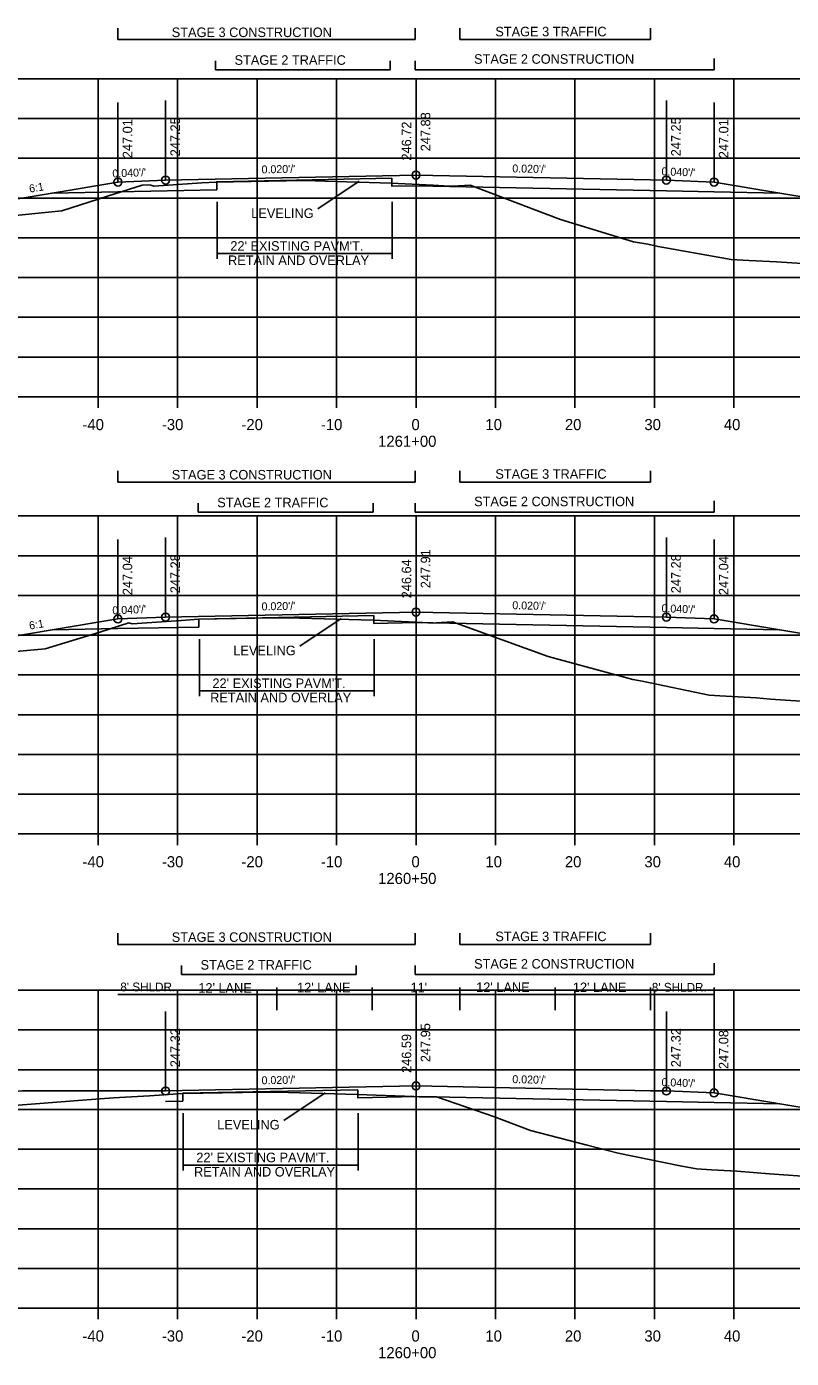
# Model space of a CAD drawing. Extents: x 1342547 to 1344156, y -1532351 to -1517216.
# Drawn here: x 1342653.9 to 1342750.1, y -1525728.6 to -1525561.1 of the extents above; entities that cross this region are included whole.
import ezdxf

# ---------------------------------------------------------------- set-up
doc = ezdxf.new("R2010")
doc.units = 0
for name, color, linetype in [('R_Alt Surface', 7, 'Continuous'), ('R_Axis', 7, 'Continuous'), ('R_Axis Annot', 7, 'Continuous'), ('R_Draft', 7, 'Continuous'), ('R_Drive', 7, 'Continuous'), ('R_Exist Surface', 7, 'Continuous'), ('R_Fin Surface', 7, 'Continuous'), ('R_Grid', 7, 'Continuous'), ('R_No Plot', 7, 'Continuous'), ('R_Xsect Elev', 7, 'Continuous'), ('R_Xsect Slope', 7, 'Continuous')]:
    doc.layers.add(name, color=color, linetype=linetype)

msp = doc.modelspace()

# ---------------------------------------------------------------- linework, layer by layer
at = {"layer": 'R_Alt Surface'}
for points in [[(1342677.81, -1525581.63), (1342677.81, -1525580.63), (1342699.84, -1525580.19)], [(1342699.84, -1525580.19), (1342699.84, -1525581.19), (1342702.87, -1525581.13)], [(1342740.37, -1525581.88), (1342734.37, -1525581.76), (1342702.87, -1525581.13)], [(1342657.09, -1525582.04), (1342665.37, -1525581.88)], [(1342665.37, -1525581.88), (1342677.81, -1525581.63)], [(1342740.37, -1525581.88), (1342748.64, -1525582.04)], [(1342675.56, -1525636.64), (1342675.56, -1525635.64), (1342697.58, -1525635.2)], [(1342697.58, -1525635.2), (1342697.58, -1525636.2), (1342702.87, -1525636.09)], [(1342740.37, -1525636.84), (1342734.37, -1525636.72), (1342702.87, -1525636.09)], [(1342657.09, -1525637.01), (1342665.37, -1525636.84)], [(1342665.37, -1525636.84), (1342675.56, -1525636.64)], [(1342740.37, -1525636.84), (1342748.64, -1525637.01)], [(1342673.53, -1525696.3), (1342673.53, -1525695.3), (1342695.55, -1525694.86)], [(1342695.55, -1525694.86), (1342695.55, -1525695.86), (1342702.87, -1525695.71)], [(1342671.37, -1525696.34), (1342673.53, -1525696.3)], [(1342740.37, -1525696.46), (1342734.37, -1525696.34), (1342702.87, -1525695.71)], [(1342740.37, -1525696.46), (1342748.64, -1525696.63)]]:
    msp.add_lwpolyline(points, dxfattribs=at)
at = {"layer": 'R_Axis'}
for p, q in [((1342562.87, -1525607.67), (1342842.87, -1525607.67)), ((1342662.87, -1525609.07), (1342662.87, -1525607.67)), ((1342672.87, -1525609.07), (1342672.87, -1525607.67)), ((1342682.87, -1525609.07), (1342682.87, -1525607.67)), ((1342692.87, -1525609.07), (1342692.87, -1525607.67)), ((1342702.87, -1525609.07), (1342702.87, -1525607.67)), ((1342712.87, -1525609.07), (1342712.87, -1525607.67)), ((1342722.87, -1525609.07), (1342722.87, -1525607.67)), ((1342732.87, -1525609.07), (1342732.87, -1525607.67)), ((1342742.87, -1525609.07), (1342742.87, -1525607.67)), ((1342562.87, -1525662.67), (1342842.87, -1525662.67)), ((1342662.87, -1525664.07), (1342662.87, -1525662.67)), ((1342672.87, -1525664.07), (1342672.87, -1525662.67)), ((1342682.87, -1525664.07), (1342682.87, -1525662.67)), ((1342692.87, -1525664.07), (1342692.87, -1525662.67)), ((1342702.87, -1525664.07), (1342702.87, -1525662.67)), ((1342712.87, -1525664.07), (1342712.87, -1525662.67)), ((1342722.87, -1525664.07), (1342722.87, -1525662.67)), ((1342732.87, -1525664.07), (1342732.87, -1525662.67)), ((1342742.87, -1525664.07), (1342742.87, -1525662.67)), ((1342562.87, -1525722.33), (1342842.87, -1525722.33)), ((1342662.87, -1525723.73), (1342662.87, -1525722.33)), ((1342672.87, -1525723.73), (1342672.87, -1525722.33)), ((1342682.87, -1525723.73), (1342682.87, -1525722.33)), ((1342692.87, -1525723.73), (1342692.87, -1525722.33)), ((1342702.87, -1525723.73), (1342702.87, -1525722.33)), ((1342712.87, -1525723.73), (1342712.87, -1525722.33)), ((1342722.87, -1525723.73), (1342722.87, -1525722.33)), ((1342732.87, -1525723.73), (1342732.87, -1525722.33)), ((1342742.87, -1525723.73), (1342742.87, -1525722.33))]:
    msp.add_line(p, q, dxfattribs=at)
at = {"layer": 'R_Draft'}
for p, q in [((1342665.37, -1525562.74), (1342665.37, -1525561.31)), ((1342702.78, -1525562.74), (1342702.78, -1525561.31)), ((1342708.37, -1525562.74), (1342708.37, -1525561.31)), ((1342732.37, -1525562.74), (1342732.37, -1525561.31)), ((1342665.37, -1525562.74), (1342702.78, -1525562.74)), ((1342708.37, -1525562.74), (1342732.37, -1525562.74)), ((1342677.64, -1525566.54), (1342677.64, -1525565.39)), ((1342699.64, -1525566.54), (1342699.64, -1525565.39)), ((1342702.78, -1525566.54), (1342702.78, -1525565.39)), ((1342740.38, -1525566.54), (1342740.38, -1525565.11)), ((1342677.64, -1525566.54), (1342699.64, -1525566.54)), ((1342702.78, -1525566.54), (1342740.38, -1525566.54)), ((1342677.87, -1525583.14), (1342677.87, -1525590.34)), ((1342699.87, -1525583.14), (1342699.87, -1525590.34)), ((1342677.87, -1525589.67), (1342699.87, -1525589.67)), ((1342665.37, -1525618.41), (1342665.37, -1525616.98)), ((1342702.78, -1525618.41), (1342702.78, -1525616.98)), ((1342708.37, -1525618.41), (1342708.37, -1525616.98)), ((1342732.37, -1525618.41), (1342732.37, -1525616.98)), ((1342665.37, -1525618.41), (1342702.78, -1525618.41)), ((1342708.37, -1525618.41), (1342732.37, -1525618.41)), ((1342675.45, -1525622.21), (1342675.45, -1525621.06)), ((1342697.46, -1525622.21), (1342697.46, -1525621.06)), ((1342702.78, -1525622.21), (1342702.78, -1525621.06)), ((1342740.38, -1525622.21), (1342740.38, -1525620.77)), ((1342675.45, -1525622.21), (1342697.46, -1525622.21)), ((1342702.78, -1525622.21), (1342740.38, -1525622.21)), ((1342675.62, -1525638.15), (1342675.62, -1525645.35)), ((1342697.62, -1525638.15), (1342697.62, -1525645.35)), ((1342675.62, -1525644.68), (1342697.62, -1525644.68)), ((1342665.37, -1525676.58), (1342665.37, -1525675.14)), ((1342665.37, -1525676.58), (1342702.78, -1525676.58)), ((1342702.78, -1525676.58), (1342702.78, -1525675.14)), ((1342708.37, -1525676.58), (1342708.37, -1525675.14)), ((1342708.37, -1525676.58), (1342732.37, -1525676.58)), ((1342732.37, -1525676.58), (1342732.37, -1525675.14)), ((1342673.36, -1525680.37), (1342673.36, -1525679.23)), ((1342695.36, -1525680.37), (1342695.36, -1525679.23)), ((1342702.78, -1525680.37), (1342702.78, -1525679.23)), ((1342740.38, -1525680.37), (1342740.38, -1525678.94)), ((1342673.36, -1525680.37), (1342695.36, -1525680.37)), ((1342702.78, -1525680.37), (1342740.38, -1525680.37)), ((1342673.59, -1525697.81), (1342673.59, -1525705.01)), ((1342695.59, -1525697.81), (1342695.59, -1525705.01)), ((1342673.59, -1525704.34), (1342695.59, -1525704.34))]:
    msp.add_line(p, q, dxfattribs=at)
at = {"layer": 'R_Drive'}
msp.add_lwpolyline([(1342581.05, -1525700.81), (1342653.37, -1525694.97), (1342671.37, -1525695.01)], dxfattribs=at)
at = {"layer": 'R_Exist Surface'}
for points in [[(1342650.35, -1525585.09), (1342658.31, -1525584.3), (1342664.04, -1525582.45), (1342668.42, -1525581.04), (1342669.2, -1525580.99), (1342669.52, -1525581.06), (1342669.88, -1525581.17), (1342675.94, -1525580.77), (1342677.73, -1525580.67), (1342686.55, -1525580.51), (1342688.92, -1525580.47), (1342691.4, -1525580.54), (1342699.76, -1525580.8), (1342705.01, -1525581.06), (1342707.03, -1525581.16), (1342707.5, -1525581.16), (1342709.7, -1525581.04), (1342717.6, -1525584.07), (1342721.06, -1525585.39), (1342729.29, -1525587.89), (1342730.22, -1525588.17), (1342732.05, -1525588.49), (1342733.33, -1525588.77), (1342742.53, -1525590.4), (1342744.75, -1525590.51), (1342748.24, -1525590.68), (1342753.37, -1525591.03)], [(1342647.41, -1525640.18), (1342656.21, -1525639.38), (1342663.1, -1525637.29), (1342666.75, -1525636.13), (1342666.88, -1525636.16), (1342667.18, -1525636.23), (1342673.33, -1525635.82), (1342675.52, -1525635.67), (1342684.99, -1525635.5), (1342686.59, -1525635.47), (1342688.22, -1525635.52), (1342697.52, -1525635.79), (1342703.69, -1525636.07), (1342705.02, -1525636.14), (1342705.39, -1525636.11), (1342707.46, -1525635.99), (1342719.5, -1525640.35), (1342730.15, -1525643.23), (1342731.33, -1525643.47), (1342739.75, -1525645.2), (1342741.08, -1525645.28), (1342745.7, -1525645.56), (1342747.49, -1525645.7), (1342752.56, -1525646.04)], [(1342651.77, -1525696.89), (1342660.92, -1525696.15), (1342664.82, -1525695.88), (1342669.33, -1525695.6), (1342673.53, -1525695.33), (1342683.56, -1525695.15), (1342684.48, -1525695.14), (1342685.37, -1525695.16), (1342695.5, -1525695.44), (1342702.58, -1525695.72), (1342703.28, -1525695.75), (1342703.45, -1525695.74), (1342705.44, -1525695.75), (1342712.74, -1525698.27), (1342717.29, -1525699.97), (1342724.39, -1525701.84), (1342728.29, -1525702.83), (1342736.12, -1525704.41), (1342738.17, -1525704.81), (1342740.04, -1525704.91), (1342743.23, -1525705.09), (1342747.35, -1525705.43), (1342751.51, -1525705.74)]]:
    msp.add_lwpolyline(points, dxfattribs=at)
at = {"layer": 'R_Fin Surface'}
for points in [[(1342612.36, -1525593.42), (1342614.23, -1525594.04), (1342643.37, -1525584.33), (1342657.09, -1525582.04), (1342665.37, -1525580.66), (1342671.37, -1525580.42), (1342673.37, -1525580.38), (1342702.87, -1525579.79), (1342732.37, -1525580.38), (1342734.37, -1525580.42), (1342740.37, -1525580.66), (1342748.64, -1525582.04), (1342762.37, -1525584.33), (1342783.17, -1525591.27)], [(1342608.75, -1525647.55), (1342613.68, -1525649.19), (1342643.37, -1525639.29), (1342657.09, -1525637.01), (1342665.37, -1525635.63), (1342671.37, -1525635.39), (1342673.37, -1525635.35), (1342702.87, -1525634.76), (1342732.37, -1525635.35), (1342734.37, -1525635.39), (1342740.37, -1525635.63), (1342748.64, -1525637.01), (1342762.37, -1525639.29), (1342783.37, -1525646.3)], [(1342671.37, -1525695.01), (1342702.87, -1525694.38), (1342732.37, -1525694.97), (1342734.37, -1525695.01), (1342740.37, -1525695.25), (1342748.64, -1525696.63), (1342762.37, -1525698.91), (1342783.8, -1525706.06)]]:
    msp.add_lwpolyline(points, dxfattribs=at)
at = {"layer": 'R_Grid'}
for p, q in [((1342562.87, -1525567.67), (1342842.87, -1525567.67)), ((1342662.87, -1525607.67), (1342662.87, -1525567.67)), ((1342672.87, -1525607.67), (1342672.87, -1525567.67)), ((1342682.87, -1525607.67), (1342682.87, -1525567.67)), ((1342692.87, -1525607.67), (1342692.87, -1525567.67)), ((1342702.87, -1525607.67), (1342702.87, -1525567.67)), ((1342712.87, -1525607.67), (1342712.87, -1525567.67)), ((1342722.87, -1525607.67), (1342722.87, -1525567.67)), ((1342732.87, -1525607.67), (1342732.87, -1525567.67)), ((1342742.87, -1525607.67), (1342742.87, -1525567.67)), ((1342562.87, -1525572.67), (1342842.87, -1525572.67)), ((1342562.87, -1525577.67), (1342842.87, -1525577.67)), ((1342562.87, -1525582.67), (1342842.87, -1525582.67)), ((1342562.87, -1525587.67), (1342842.87, -1525587.67)), ((1342562.87, -1525592.67), (1342842.87, -1525592.67)), ((1342562.87, -1525597.67), (1342842.87, -1525597.67)), ((1342562.87, -1525602.67), (1342842.87, -1525602.67)), ((1342562.87, -1525607.67), (1342842.87, -1525607.67)), ((1342562.87, -1525622.67), (1342842.87, -1525622.67)), ((1342662.87, -1525662.67), (1342662.87, -1525622.67)), ((1342672.87, -1525662.67), (1342672.87, -1525622.67)), ((1342682.87, -1525662.67), (1342682.87, -1525622.67)), ((1342692.87, -1525662.67), (1342692.87, -1525622.67)), ((1342702.87, -1525662.67), (1342702.87, -1525622.67)), ((1342712.87, -1525662.67), (1342712.87, -1525622.67)), ((1342722.87, -1525662.67), (1342722.87, -1525622.67)), ((1342732.87, -1525662.67), (1342732.87, -1525622.67)), ((1342742.87, -1525662.67), (1342742.87, -1525622.67)), ((1342562.87, -1525627.67), (1342842.87, -1525627.67)), ((1342562.87, -1525632.67), (1342842.87, -1525632.67)), ((1342562.87, -1525637.67), (1342842.87, -1525637.67)), ((1342562.87, -1525642.67), (1342842.87, -1525642.67)), ((1342562.87, -1525647.67), (1342842.87, -1525647.67)), ((1342562.87, -1525652.67), (1342842.87, -1525652.67)), ((1342562.87, -1525657.67), (1342842.87, -1525657.67)), ((1342562.87, -1525662.67), (1342842.87, -1525662.67)), ((1342562.87, -1525682.33), (1342842.87, -1525682.33)), ((1342662.87, -1525722.33), (1342662.87, -1525682.33)), ((1342672.87, -1525722.33), (1342672.87, -1525682.33)), ((1342682.87, -1525722.33), (1342682.87, -1525682.33)), ((1342692.87, -1525722.33), (1342692.87, -1525682.33)), ((1342702.87, -1525722.33), (1342702.87, -1525682.33)), ((1342712.87, -1525722.33), (1342712.87, -1525682.33)), ((1342722.87, -1525722.33), (1342722.87, -1525682.33)), ((1342732.87, -1525722.33), (1342732.87, -1525682.33)), ((1342742.87, -1525722.33), (1342742.87, -1525682.33)), ((1342562.87, -1525687.33), (1342842.87, -1525687.33)), ((1342562.87, -1525692.33), (1342842.87, -1525692.33)), ((1342562.87, -1525697.33), (1342842.87, -1525697.33)), ((1342562.87, -1525702.33), (1342842.87, -1525702.33)), ((1342562.87, -1525707.33), (1342842.87, -1525707.33)), ((1342562.87, -1525712.33), (1342842.87, -1525712.33)), ((1342562.87, -1525717.33), (1342842.87, -1525717.33)), ((1342562.87, -1525722.33), (1342842.87, -1525722.33))]:
    msp.add_line(p, q, dxfattribs=at)
at = {"layer": 'R_No Plot'}
for centre in [(1342702.87, -1525579.79), (1342665.37, -1525580.66), (1342671.37, -1525580.42), (1342734.37, -1525580.42), (1342740.37, -1525580.66), (1342702.87, -1525634.76), (1342665.37, -1525635.63), (1342671.37, -1525635.39), (1342734.37, -1525635.39), (1342740.37, -1525635.63), (1342671.37, -1525695.01), (1342702.87, -1525694.38), (1342734.37, -1525695.01), (1342740.37, -1525695.25)]:
    msp.add_circle(centre, 0.5, dxfattribs=at)
at = {"layer": 'R_Xsect Elev'}
for p, q in [((1342665.37, -1525580.66), (1342665.37, -1525570.66)), ((1342671.37, -1525580.42), (1342671.37, -1525570.42)), ((1342702.87, -1525579.79), (1342702.87, -1525569.79)), ((1342702.87, -1525580.96), (1342702.87, -1525570.96)), ((1342734.37, -1525580.42), (1342734.37, -1525570.42)), ((1342740.37, -1525580.66), (1342740.37, -1525570.66)), ((1342695.72, -1525580.56), (1342690.52, -1525584.05)), ((1342665.37, -1525635.63), (1342665.37, -1525625.63)), ((1342671.37, -1525635.39), (1342671.37, -1525625.39)), ((1342702.87, -1525634.76), (1342702.87, -1525624.76)), ((1342702.87, -1525636.03), (1342702.87, -1525626.03)), ((1342734.37, -1525635.39), (1342734.37, -1525625.39)), ((1342740.37, -1525635.63), (1342740.37, -1525625.63)), ((1342693.47, -1525635.57), (1342688.27, -1525639.06)), ((1342740.37, -1525682.85), (1342665.37, -1525682.85)), ((1342685.37, -1525684.86), (1342685.37, -1525682)), ((1342697.37, -1525684.86), (1342697.37, -1525682)), ((1342708.37, -1525684.86), (1342708.37, -1525682)), ((1342720.37, -1525684.86), (1342720.37, -1525682)), ((1342732.37, -1525684.86), (1342732.37, -1525682)), ((1342740.37, -1525695.25), (1342740.37, -1525682)), ((1342702.87, -1525694.38), (1342702.87, -1525684.38)), ((1342671.37, -1525695.01), (1342671.37, -1525685.01)), ((1342702.87, -1525695.74), (1342702.87, -1525685.74)), ((1342734.37, -1525695.01), (1342734.37, -1525685.01)), ((1342740.37, -1525695.25), (1342740.37, -1525685.25)), ((1342740.37, -1525695.25), (1342740.37, -1525685.25)), ((1342691.44, -1525695.23), (1342686.24, -1525698.72))]:
    msp.add_line(p, q, dxfattribs=at)

# ---------------------------------------------------------------- texts
at = {"layer": 'R_Axis Annot'}
for s, p in [('-40', (1342660.9, -1525611.87)), ('-30', (1342670.9, -1525611.87)), ('-20', (1342680.9, -1525611.87)), ('-10', (1342690.9, -1525611.87)), ('0', (1342702.3, -1525611.87)), ('10', (1342711.6, -1525611.87)), ('20', (1342721.6, -1525611.87)), ('30', (1342731.6, -1525611.87)), ('40', (1342741.6, -1525611.87)), ('1261+00', (1342698.1, -1525613.97)), ('-40', (1342660.9, -1525666.87)), ('-30', (1342670.9, -1525666.87)), ('-20', (1342680.9, -1525666.87)), ('-10', (1342690.9, -1525666.87)), ('0', (1342702.3, -1525666.87)), ('10', (1342711.6, -1525666.87)), ('20', (1342721.6, -1525666.87)), ('30', (1342731.6, -1525666.87)), ('40', (1342741.6, -1525666.87)), ('1260+50', (1342698.1, -1525668.97)), ('-40', (1342660.9, -1525726.53)), ('-30', (1342670.9, -1525726.53)), ('-20', (1342680.9, -1525726.53)), ('-10', (1342690.9, -1525726.53)), ('0', (1342702.3, -1525726.53)), ('10', (1342711.6, -1525726.53)), ('20', (1342721.6, -1525726.53)), ('30', (1342731.6, -1525726.53)), ('40', (1342741.6, -1525726.53)), ('1260+00', (1342698.1, -1525728.63))]:
    msp.add_text(s, height=1.4, dxfattribs=at).set_placement(p)
at = {"layer": 'R_Draft'}
for s, p in [('STAGE 3 CONSTRUCTION', (1342672.14, -1525562.42)), ('STAGE 3 TRAFFIC', (1342712.85, -1525562.33)), ('STAGE 2 TRAFFIC', (1342680.04, -1525565.91)), ('STAGE 2 CONSTRUCTION', (1342710.18, -1525565.78)), ("22' EXISTING PAVM'T.", (1342679.51, -1525589.3)), ('RETAIN AND OVERLAY', (1342679.22, -1525591.1)), ('STAGE 3 CONSTRUCTION', (1342672.14, -1525618.08)), ('STAGE 3 TRAFFIC', (1342712.85, -1525617.99)), ('STAGE 2 TRAFFIC', (1342677.86, -1525621.58)), ('STAGE 2 CONSTRUCTION', (1342710.18, -1525621.44)), ("22' EXISTING PAVM'T.", (1342677.26, -1525644.31)), ('RETAIN AND OVERLAY', (1342676.97, -1525646.11)), ('STAGE 3 TRAFFIC', (1342712.85, -1525676.16)), ('STAGE 3 CONSTRUCTION', (1342672.14, -1525676.25)), ('STAGE 2 TRAFFIC', (1342675.76, -1525679.74)), ('STAGE 2 CONSTRUCTION', (1342710.18, -1525679.61)), ("22' EXISTING PAVM'T.", (1342675.23, -1525703.97)), ('RETAIN AND OVERLAY', (1342674.94, -1525705.77))]:
    msp.add_text(s, height=1.2, dxfattribs=at).set_placement(p)
at = {"layer": 'R_Xsect Elev'}
for s, p in [('247.25', (1342673.17, -1525577.42)), ('247.88', (1342704.67, -1525576.79)), ('247.25', (1342736.17, -1525577.42)), ('247.01', (1342667.17, -1525577.66)), ('246.72', (1342702.27, -1525577.96)), ('247.01', (1342742.17, -1525577.66)), ('247.04', (1342667.17, -1525632.63)), ('247.28', (1342673.17, -1525632.39)), ('247.91', (1342704.67, -1525631.76)), ('247.28', (1342736.17, -1525632.39)), ('247.04', (1342742.17, -1525632.63)), ('246.64', (1342702.27, -1525633.03)), ('247.95', (1342704.67, -1525691.38)), ('247.32', (1342673.17, -1525692.01)), ('246.59', (1342702.27, -1525692.74)), ('247.32', (1342736.17, -1525692.01)), ('247.08', (1342742.17, -1525692.25))]:
    msp.add_text(s, height=1.2, rotation=90, dxfattribs=at).set_placement(p)
for s, height, p in [('LEVELING', 1.2, (1342682.14, -1525585.18)), ('LEVELING', 1.2, (1342679.89, -1525640.19)), ("8' SHLDR.", 1.1, (1342665.67, -1525682.47)), ("12' LANE", 1.2, (1342675.48, -1525682.64)), ("12' LANE", 1.2, (1342687.91, -1525682.59)), ("11'", 1.2, (1342702.18, -1525682.59)), ("12' LANE", 1.2, (1342710.44, -1525682.56)), ("12' LANE", 1.2, (1342722.61, -1525682.57)), ("8' SHLDR.", 1.1, (1342732.54, -1525682.51)), ('LEVELING', 1.2, (1342677.86, -1525699.85))]:
    msp.add_text(s, height=height, dxfattribs=at).set_placement(p)
at = {"layer": 'R_Xsect Slope'}
for s, rotation, p in [("0.040'/'", 2.2906, (1342664.69, -1525580.09)), ("0.020'/'", 1.1458, (1342683.45, -1525579.58)), ("0.020'/'", 358.8542, (1342714.98, -1525579.44)), ("0.040'/'", 357.7088, (1342733.74, -1525579.8)), ('6:1', 9.4623, (1342654.28, -1525582)), ("0.040'/'", 2.2906, (1342664.69, -1525635.05)), ("0.020'/'", 1.1458, (1342683.45, -1525634.55)), ("0.020'/'", 358.8542, (1342714.98, -1525634.4)), ("0.040'/'", 357.7088, (1342733.74, -1525634.76)), ('6:1', 9.4623, (1342654.28, -1525636.97)), ("0.020'/'", 1.1458, (1342683.45, -1525694.17)), ("0.020'/'", 358.8542, (1342714.98, -1525694.02)), ("0.040'/'", 357.7089, (1342733.74, -1525694.38))]:
    msp.add_text(s, height=1, rotation=rotation, dxfattribs=at).set_placement(p)

doc.saveas('drawing.dxf')
